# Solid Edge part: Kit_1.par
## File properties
Author: bmolnar
Last saved by: bmolnar
Revision: 77
Sűrűség: 0,000 kg/m^3
Pontosság: 0,990
Username: bmolnar
Dokumentum tartalom típus: 0
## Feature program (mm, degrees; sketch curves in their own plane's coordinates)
base feature "unnamed BaseFeature 1"
sketch for "unnamed Hole 1" plane through (0, 0, 99) normal (0, 0, 1) x-axis (0, 1, 0)
hole "unnamed Hole 1" through
sketch for "unnamed Hole 2" plane through (0, 0, 99) normal (0, 0, 1) x-axis (0, 1, 0)
  hole centre (28.25, 28.25) bore radius 3.3235
hole "unnamed Hole 2" through
sketch for "unnamed Hole 3" plane through (0, 0, 99) normal (0, 0, 1) x-axis (0, 1, 0)
  hole centre (28.25, -28.25) bore radius 3.3235
hole "unnamed Hole 3" through
sketch for "unnamed Hole 4" plane through (0, 0, 99) normal (0, 0, 1) x-axis (0, 1, 0)
  hole centre (-28.25, -28.25) bore radius 3.3235
hole "unnamed Hole 4" through
pattern "unnamed Pattern 1" of "unnamed Hole 1", "unnamed Hole 2", "unnamed Hole 3", "unnamed Hole 4"
sketch for "Furat_5" plane through (-38.5, 0, 123.75) normal (1, 0, 0) x-axis (0, -1, 0)
  hole centre (0, 32.25) bore radius 4.283
hole "Furat_5" nominal diameter 9.728 finite  ThreadDepth = 10 mm
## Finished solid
Body 1: solid body, 308 faces, 750 edges, 456 vertices.
  Faces by surface: plane 141, cylinder 75, swept 61, cone 20, torus 10, spline 1
  Edges by curve: line 431, circle 154, spline 126, ellipse 30, curve on surface 9
Bounding box of the edges (mm; curved faces can reach further): 77.000 x 77.000 x 13.750, from (-38.5, -38.5, 85.25) to (38.5, 38.5, 99).
Cylindrical faces by radius (mm): R0.2 x48, R0.2008 x2, R0.2009 x2, R0.402 x1, R0.4899 x1, R3.3235 x4, R4.283 x1, R4.9 x4, R5.15 x4, R5.25 x4, R8.27 x1, R8.85 x1, R9 x1, R10.25 x1
Conical faces (half-angle, radius in mm at the cone's reference point): 0.5 deg R12 x4, 0.5 deg R13.5 x2, 7 deg R9.5925 x1, 14 deg R8.135 x1, 14 deg R8.4811 x1, 17 deg R8.135 x1, 23 deg R8.829 x1, 42.5 deg R8.1233 x1, 45 deg R3.6735 x4, 45 deg R9 x1, 84 deg R8.4608 x1, 85 deg R9.9463 x1, 87 deg R8.1765 x1
Toroidal faces (ring radius, tube radius in mm): R4.7 r0.2 x8, R8.8057 r0.2025 x1, R9.2522 r0.2925 x1
Planar faces by outward normal: +x 12, +y 13, +z 19, -x 15, -y 14, -z 1, oblique 67
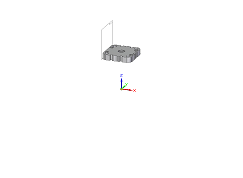
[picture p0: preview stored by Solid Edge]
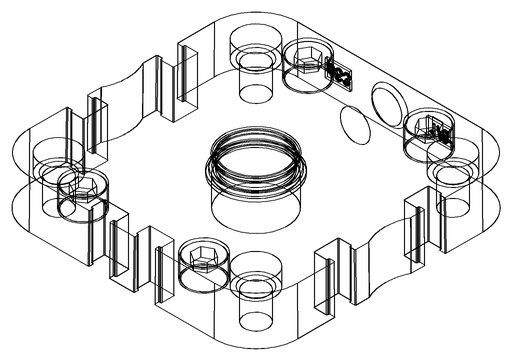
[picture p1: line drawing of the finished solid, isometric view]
